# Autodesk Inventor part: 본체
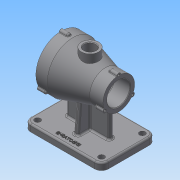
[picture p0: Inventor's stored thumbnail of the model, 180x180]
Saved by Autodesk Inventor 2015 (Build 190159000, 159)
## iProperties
Created: 2020-03
Part Number: 본체
Material: 일반
Document SubType Name: Modeling
Designer: user
Density: 1 g/cm^3
Appearance: 기본값
Author: user
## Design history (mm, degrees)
sketch "스케치1"
  geometry: 1 further point
node "작업 평면1"
sketch "스케치2"
  geometry: L1 (-67.5, -47.5)-(67.5, -47.5); L2 (67.5, -47.5)-(67.5, 47.5); L3 (67.5, 47.5)-(-67.5, 47.5); L4 (-67.5, 47.5)-(-67.5, -47.5); L5 (-67.5, -47.5)-(67.5, 47.5); L6 (67.5, -47.5)-(-67.5, 47.5); 1 further point
  constraints: 12 end point, 2 midpoint, 2 parallel, 1 horizontal, 1 perpendicular
  dimensions: "d1" = 135 distance of L3.end L2.end; "d2" = 95 distance of L2.end L1.end
extrude "돌출1" new body sketch "스케치2" distance "d3" = 12; taper "d4" = 0 deg
sketch "스케치3"
  geometry: L1 (-50, 0)-(50, 0); L2 (-50, 0)-(-50, 44); L3 (-50, 44)-(-30, 44); L4 (50, 0)-(50, 27.5); L5 (50, 27.5)-(27, 27.5); L6 (27, 27.5)-(-30, 44); 2 further points
  constraints: 12 end point, 2 perpendicular, 2 vertical, 1 coincident, 1 horizontal, 1 midpoint
  dimensions: "d5" = 100 distance of L1.start L1.end; "d6" = 44 distance of L1.start L2.end; "d7" = 20 distance of L2.end L3.end; "d8" = 27.5 distance of L1.end L4.end; "d9" = 23 distance of L4.end L5.end
revolve "회전1" sketch "스케치3" stored, may be unused: angle "d10" = 90 deg
sketch "스케치4"
  geometry: L1 (0, 0)-(37, 0); L2 (37, 0)-(37, -82); L3 (37, -82)-(0, -82); L4 (0, 0)-(-37, 0); L5 (-37, 0)-(-37, -82); L6 (-37, -82)-(0, -82)
  constraints: 12 end point, 3 horizontal, 3 perpendicular
  dimensions: "d11" = 37 distance of L3.end L2.end; "d12" = 37 distance of L1.start L4.end
extrude "돌출2" join sketch "스케치4" stored distance "d13" = 8; taper "d14" = 0 deg
sketch "스케치8"
  geometry: L1 (0, 0)-(0, -75); L2 (0, -75)-(-25, -75); L3 (-25, -75)-(-20.363, -22); L4 (-20.363, -22)-(0, -22); L5 (0, -75)-(25, -75); L6 (0, -75)-(25, -75); L7 (25, -75)-(20.363, -22); L8 (20.363, -22)-(0, -22)
  constraints: 16 end point, 3 perpendicular, 2 horizontal, 1 collinear, 1 point on line, 1 vertical
  dimensions: "d24" = 75 distance of L1.start L1.end; "d25" = 25 distance of L1.end L2.end; "d26" = 85 deg angle of L2 L3; "d27" = 25 distance of L1.end L5.end; "d28" = 0 distance between parallel lines of L5 L6 (derived); "d29" = 85 deg angle of L7 L5
extrude "돌출6" join sketch "스케치8" stored distance "d30" = 8; taper "d31" = 0 deg
sketch "스케치5"
  geometry: C1 r 44 at (0, 0) reference; C2 r 36 at (0, 0)
  constraints: 1 centre point, 1 coincident
  dimensions: "d15" = 72 diameter of C2
extrude "돌출3" cut sketch "스케치5" distance "d16" = 23; taper "d17" = 0 deg
sketch "스케치6"
  geometry: C1 r 36 at (0, 0) reference; C2 r 26 at (0, 0)
  constraints: 1 centre point, 1 coincident
  dimensions: "d18" = 52 diameter of C2
extrude "돌출4" cut sketch "스케치6" distance "d19" = 47; taper "d20" = 0 deg
sketch "스케치7"
  geometry: C1 r 26 at (0, 0) reference; C2 r 20 at (0, 0)
  constraints: 1 centre point, 1 coincident
  dimensions: "d21" = 40 diameter of C2
extrude "돌출5" cut sketch "스케치7" stored distance "d22" = 47; taper "d23" = 0 deg
sketch "스케치9"
  geometry: C1 r 3.5 at (44, 0); 1 further point
  constraints: 1 centre point, 1 horizontal alignment, 1 other
  dimensions: "d32" = 7 diameter of C1
extrude "돌출7" join sketch "스케치9" distance "d33" = 15; taper "d34" = 0 deg
sketch "스케치10"
  geometry: A1 r 3.5 centre (0, 0) between (-0.139, -3.497) and (-0.139, 3.497) reference; 1 further point
  constraints: 1 coincident
hole "구멍1" sketch "스케치10" at (0, 0) diameter "d35" = 4.134; stored, may be unused: countersink angle "d39" = 90 deg, drill point angle "d41" = 118 deg; dims "d36" = 9, "d37" = 4, "d38" = 2, "d40" = 11
sketch "스케치11"
  geometry: C1 r 3.5 at (-27.5, 0); 1 further point
  constraints: 1 centre point, 1 horizontal alignment, 1 other
  dimensions: "d45" = 7 diameter of C1
extrude "돌출8" join sketch "스케치11" distance "d46" = 15; taper "d47" = 0 deg
sketch "스케치12"
  geometry: A1 r 3.5 centre (0, 0) between (0.223, 3.493) and (0.223, -3.493) reference; 1 further point
  constraints: 1 coincident
hole "구멍2" sketch "스케치12" at (0, 0) diameter "d48" = 4.134; stored, may be unused: countersink angle "d52" = 90 deg, drill point angle "d54" = 118 deg; dims "d49" = 9, "d50" = 4, "d51" = 2, "d53" = 11
node "작업 평면2"
sketch "스케치13"
  geometry: C1 r 15 at (0, 0); 1 further point
  constraints: 1 centre point, 1 coincident
  dimensions: "d56" = 30 diameter of C1
extrude "돌출9" join sketch "스케치13" distance "d57" = 15; taper "d58" = 0 deg
sketch "스케치14"
  geometry: C1 r 15 at (0, 0) reference; C2 r 10 at (0, 0)
  constraints: 1 centre point, 1 coincident
  dimensions: "d59" = 20 diameter of C2
extrude "돌출10" cut sketch "스케치14" distance "d60" = 30; taper "d61" = 0 deg
fillet "모깎기1" dims "d62" = 12
sketch "스케치15"
  geometry: C1 r 5 at (-55.5, -35.5); C2 r 5 at (-55.5, 35.5); C3 r 5 at (55.5, 35.5); C4 r 5 at (55.5, -35.5); A1 r 12 centre (-55.5, 35.5) between (-55.5, 47.5) and (-67.5, 35.5) reference; A2 r 12 centre (-55.5, -35.5) between (-67.5, -35.5) and (-55.5, -47.5) reference; A3 r 12 centre (55.5, -35.5) between (55.5, -47.5) and (67.5, -35.5) reference; A4 r 12 centre (55.5, 35.5) between (67.5, 35.5) and (55.5, 47.5) reference; 1 further point
  constraints: 4 centre point, 4 coincident
  dimensions: "d63" = 10 diameter of C1; "d64" = 10 diameter of C2; "d65" = 10 diameter of C3; "d66" = 10 diameter of C4
extrude "돌출11" cut sketch "스케치15" distance "d67" = 30; taper "d68" = 0 deg
fillet "모깎기2" dims "d69" = 3
fillet "모깎기3" dims "d73" = 1
fillet "모깎기4" dims "d79" = 3
fillet "모깎기5" dims "d80" = 3
chamfer "모따기1" distance "d81" = 1; stored, may be unused: second distance "d82" = 2, angle "d83" = 45 deg
fillet "모깎기6" dims "d84" = 3
fillet "모깎기7" dims "d85" = 3
node "작업 평면4"
sketch "스케치17"
  geometry: L1 (-55.5, -47.5)-(55.5, -47.5) reference; 2 further points
  constraints: 1 vertical alignment, 1 other
  dimensions: "d87" = 10 distance from line of L1 point (0, -37.5)
feature "엠보싱1" sketch "스케치17" dims "d11" = 37, "d12" = 37, "d88" = 1, "d89" = 0
node "솔리드1"
pattern_circular "원형 패턴3" dims "d75" = 360 deg
other parameters: "d0" = -87, "d55" = 45, "d86" = 27.5
